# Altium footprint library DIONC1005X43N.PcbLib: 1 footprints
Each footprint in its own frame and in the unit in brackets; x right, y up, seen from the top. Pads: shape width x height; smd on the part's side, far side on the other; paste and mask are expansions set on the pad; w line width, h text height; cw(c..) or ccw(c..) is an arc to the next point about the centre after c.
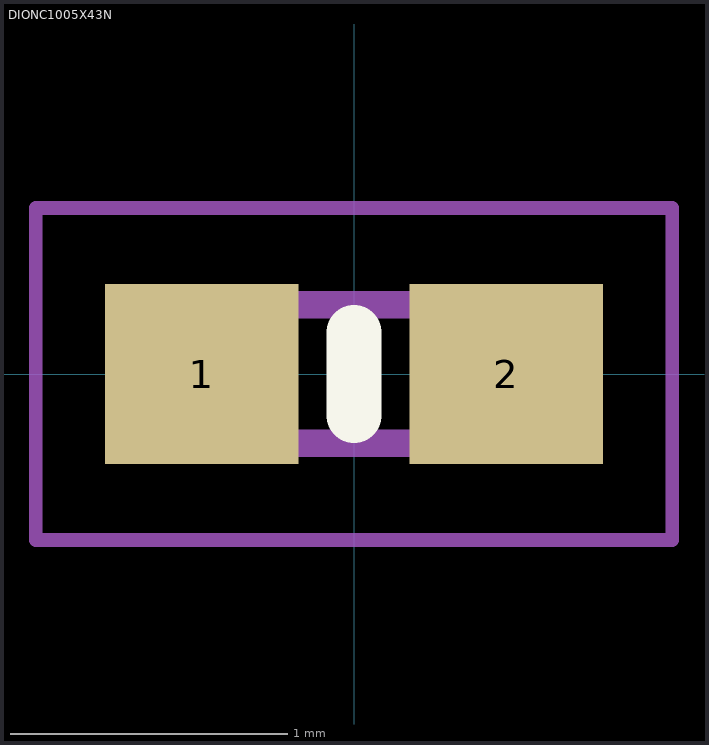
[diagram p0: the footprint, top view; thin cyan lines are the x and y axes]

## DIONC1005X43N [mm]
pads (2):
  rect 0.7x0.65 smd: 1(-0.55,0) 2(0.55,0)
Top Overlay:
  lines w0.2: 0,-0.15 0,0.15
Mechanical 15:
  lines w0.1: -0.5,-0.25 0.5,-0.25 0.5,0.25 -0.5,0.25 -0.5,-0.25
Mechanical 20:
  lines w0.05: -1.15,-0.6 1.15,-0.6 1.15,0.6 -1.15,0.6 -1.15,-0.6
